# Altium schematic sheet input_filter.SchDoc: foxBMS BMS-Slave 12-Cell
size A3; DocumentNumber: 4; SheetNumber: 4; SheetTotal: 15; AUTHOR: Fraunhofer IISB foxBMS Team; SheetDescription: Primary Voltage Measurement
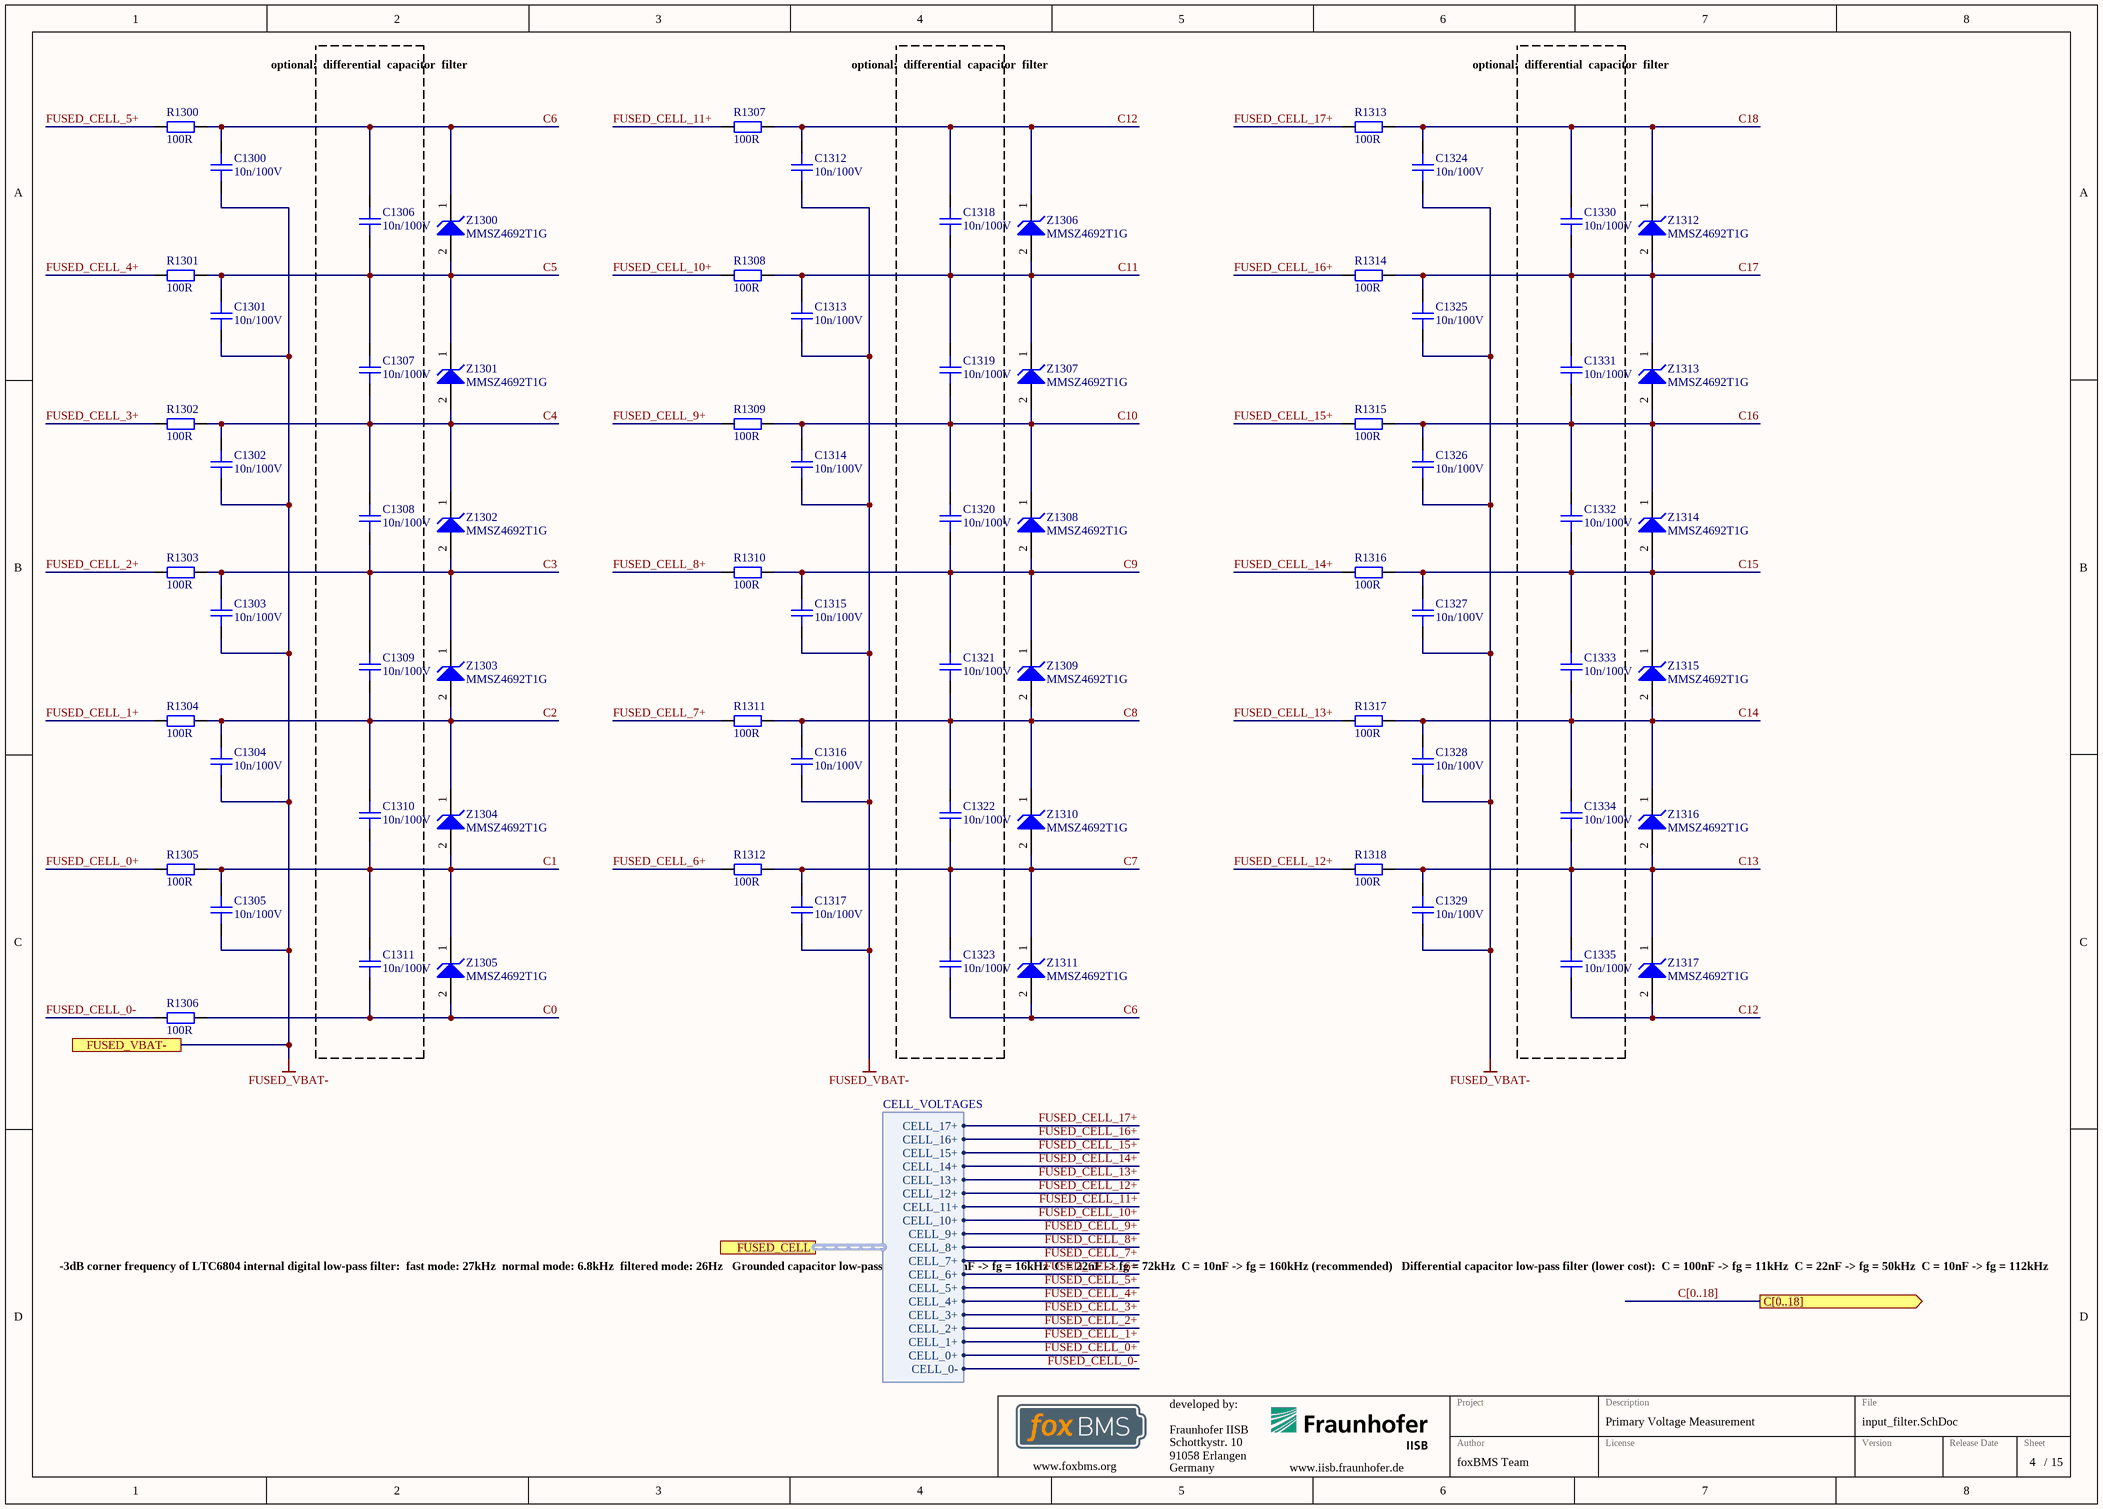
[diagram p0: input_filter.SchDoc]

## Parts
C1300  10n/100V  [CAPC1608X08N]
C1301  10n/100V  [CAPC1608X08N]
C1302  10n/100V  [CAPC1608X08N]
C1303  10n/100V  [CAPC1608X08N]
C1304  10n/100V  [CAPC1608X08N]
C1305  10n/100V  [CAPC1608X08N]
C1306  10n/100V  [CAPC1608X08N]
C1307  10n/100V  [CAPC1608X08N]
C1308  10n/100V  [CAPC1608X08N]
C1309  10n/100V  [CAPC1608X08N]
C1310  10n/100V  [CAPC1608X08N]
C1311  10n/100V  [CAPC1608X08N]
C1312  10n/100V  [CAPC1608X08N]
C1313  10n/100V  [CAPC1608X08N]
C1314  10n/100V  [CAPC1608X08N]
C1315  10n/100V  [CAPC1608X08N]
C1316  10n/100V  [CAPC1608X08N]
C1317  10n/100V  [CAPC1608X08N]
C1318  10n/100V  [CAPC1608X08N]
C1319  10n/100V  [CAPC1608X08N]
C1320  10n/100V  [CAPC1608X08N]
C1321  10n/100V  [CAPC1608X08N]
C1322  10n/100V  [CAPC1608X08N]
C1323  10n/100V  [CAPC1608X08N]
C1324  10n/100V  [CAPC1608X08N]
C1325  10n/100V  [CAPC1608X08N]
C1326  10n/100V  [CAPC1608X08N]
C1327  10n/100V  [CAPC1608X08N]
C1328  10n/100V  [CAPC1608X08N]
C1329  10n/100V  [CAPC1608X08N]
C1330  10n/100V  [CAPC1608X08N]
C1331  10n/100V  [CAPC1608X08N]
C1332  10n/100V  [CAPC1608X08N]
C1333  10n/100V  [CAPC1608X08N]
C1334  10n/100V  [CAPC1608X08N]
C1335  10n/100V  [CAPC1608X08N]
R1300  100R  [RESC1608X05N]
R1301  100R  [RESC1608X05N]
R1302  100R  [RESC1608X05N]
R1303  100R  [RESC1608X05N]
R1304  100R  [RESC1608X05N]
R1305  100R  [RESC1608X05N]
R1306  100R  [RESC1608X05N]
R1307  100R  [RESC1608X05N]
R1308  100R  [RESC1608X05N]
R1309  100R  [RESC1608X05N]
R1310  100R  [RESC1608X05N]
R1311  100R  [RESC1608X05N]
R1312  100R  [RESC1608X05N]
R1313  100R  [RESC1608X05N]
R1314  100R  [RESC1608X05N]
R1315  100R  [RESC1608X05N]
R1316  100R  [RESC1608X05N]
R1317  100R  [RESC1608X05N]
R1318  100R  [RESC1608X05N]
Z1300  MMSZ4692T1G  [ONSC-SOD-123-2-425-04_V]
Z1301  MMSZ4692T1G  [ONSC-SOD-123-2-425-04_V]
Z1302  MMSZ4692T1G  [ONSC-SOD-123-2-425-04_V]
Z1303  MMSZ4692T1G  [ONSC-SOD-123-2-425-04_V]
Z1304  MMSZ4692T1G  [ONSC-SOD-123-2-425-04_V]
Z1305  MMSZ4692T1G  [ONSC-SOD-123-2-425-04_V]
Z1306  MMSZ4692T1G  [ONSC-SOD-123-2-425-04_V]
Z1307  MMSZ4692T1G  [ONSC-SOD-123-2-425-04_V]
Z1308  MMSZ4692T1G  [ONSC-SOD-123-2-425-04_V]
Z1309  MMSZ4692T1G  [ONSC-SOD-123-2-425-04_V]
Z1310  MMSZ4692T1G  [ONSC-SOD-123-2-425-04_V]
Z1311  MMSZ4692T1G  [ONSC-SOD-123-2-425-04_V]
Z1312  MMSZ4692T1G  [ONSC-SOD-123-2-425-04_V]
Z1313  MMSZ4692T1G  [ONSC-SOD-123-2-425-04_V]
Z1314  MMSZ4692T1G  [ONSC-SOD-123-2-425-04_V]
Z1315  MMSZ4692T1G  [ONSC-SOD-123-2-425-04_V]
Z1316  MMSZ4692T1G  [ONSC-SOD-123-2-425-04_V]
Z1317  MMSZ4692T1G  [ONSC-SOD-123-2-425-04_V]

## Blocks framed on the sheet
optional: / differential / capacitor / filter: C1306-C1311
optional: / differential / capacitor / filter: C1318-C1323
optional: / differential / capacitor / filter: C1330-C1335

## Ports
C[0..18] (out), FUSED_CELL (harness CELL_VOLTAGES), FUSED_VBAT-

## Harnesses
CELL_VOLTAGES: CELL_0-, CELL_0+, CELL_1+, CELL_10+, CELL_11+, CELL_12+, CELL_13+, CELL_14+, CELL_15+, CELL_16+, CELL_17+, CELL_2+, CELL_3+, CELL_4+, CELL_5+, CELL_6+, CELL_7+, CELL_8+, CELL_9+

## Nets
FUSED_VBAT-: C1300.2 C1301.2 C1302.2 C1303.2 C1304.2 C1305.2 C1312.2 C1313.2 C1314.2 C1315.2 C1316.2 C1317.2 C1324.2 C1325.2 C1326.2 C1327.2 C1328.2 C1329.2 ; port FUSED_VBAT-
C0: C1311.2 R1306.2 Z1305.2(A)
C1: C1305.1 C1310.2 C1311.1 R1305.2 Z1304.2(A) Z1305.1(K)
C2: C1304.1 C1309.2 C1310.1 R1304.2 Z1303.2(A) Z1304.1(K)
C3: C1303.1 C1308.2 C1309.1 R1303.2 Z1302.2(A) Z1303.1(K)
C4: C1302.1 C1307.2 C1308.1 R1302.2 Z1301.2(A) Z1302.1(K)
C5: C1301.1 C1306.2 C1307.1 R1301.2 Z1300.2(A) Z1301.1(K)
C6: C1300.1 C1306.1 C1323.2 R1300.2 Z1300.1(K) Z1311.2(A)
C7: C1317.1 C1322.2 C1323.1 R1312.2 Z1310.2(A) Z1311.1(K)
C8: C1316.1 C1321.2 C1322.1 R1311.2 Z1309.2(A) Z1310.1(K)
C9: C1315.1 C1320.2 C1321.1 R1310.2 Z1308.2(A) Z1309.1(K)
C10: C1314.1 C1319.2 C1320.1 R1309.2 Z1307.2(A) Z1308.1(K)
C11: C1313.1 C1318.2 C1319.1 R1308.2 Z1306.2(A) Z1307.1(K)
C12: C1312.1 C1318.1 C1335.2 R1307.2 Z1306.1(K) Z1317.2(A)
C13: C1329.1 C1334.2 C1335.1 R1318.2 Z1316.2(A) Z1317.1(K)
C14: C1328.1 C1333.2 C1334.1 R1317.2 Z1315.2(A) Z1316.1(K)
C15: C1327.1 C1332.2 C1333.1 R1316.2 Z1314.2(A) Z1315.1(K)
C16: C1326.1 C1331.2 C1332.1 R1315.2 Z1313.2(A) Z1314.1(K)
C17: C1325.1 C1330.2 C1331.1 R1314.2 Z1312.2(A) Z1313.1(K)
C18: C1324.1 C1330.1 R1313.2 Z1312.1(K)
FUSED_CELL_0+: R1305.1 ; port FUSED_CELL.CELL_0+
FUSED_CELL_0-: R1306.1 ; port FUSED_CELL.CELL_0-
FUSED_CELL_1+: R1304.1 ; port FUSED_CELL.CELL_1+
FUSED_CELL_2+: R1303.1 ; port FUSED_CELL.CELL_2+
FUSED_CELL_3+: R1302.1 ; port FUSED_CELL.CELL_3+
FUSED_CELL_4+: R1301.1 ; port FUSED_CELL.CELL_4+
FUSED_CELL_5+: R1300.1 ; port FUSED_CELL.CELL_5+
FUSED_CELL_6+: R1312.1 ; port FUSED_CELL.CELL_6+
FUSED_CELL_7+: R1311.1 ; port FUSED_CELL.CELL_7+
FUSED_CELL_8+: R1310.1 ; port FUSED_CELL.CELL_8+
FUSED_CELL_9+: R1309.1 ; port FUSED_CELL.CELL_9+
FUSED_CELL_10+: R1308.1 ; port FUSED_CELL.CELL_10+
FUSED_CELL_11+: R1307.1 ; port FUSED_CELL.CELL_11+
FUSED_CELL_12+: R1318.1 ; port FUSED_CELL.CELL_12+
FUSED_CELL_13+: R1317.1 ; port FUSED_CELL.CELL_13+
FUSED_CELL_14+: R1316.1 ; port FUSED_CELL.CELL_14+
FUSED_CELL_15+: R1315.1 ; port FUSED_CELL.CELL_15+
FUSED_CELL_16+: R1314.1 ; port FUSED_CELL.CELL_16+
FUSED_CELL_17+: R1313.1 ; port FUSED_CELL.CELL_17+

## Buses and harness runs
bus C[0..18] = port C[0..18]

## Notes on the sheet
- -3dB corner frequency of LTC6804 internal digital low-pass filter:
  fast mode: 27kHz
  normal mode: 6.8kHz
  filtered mode: 26Hz
  Grounded capacitor low-pass filter:
  C = 100nF -> fg = 16kHz
  C = 22nF -> fg = 72kHz
  C = 10nF -> fg = 160kHz (recommended)
  Differential capacitor low-pass filter (lower cost):
  C = 100nF -> fg = 11kHz
  C = 22nF -> fg = 50kHz
  C = 10nF -> fg = 112kHz

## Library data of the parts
C1300-C1335 = gen_C_ceramic_10n_100V_X7R_0603: MLCC; Capacitance: 10n; Rated Voltage: 100V; Dielectric: X7R; Case EIA: 0603; Case Metric: 1608; Automotive Qualified: True
R1300-R1318 = gen_R_100R_0603: SMD Resistor 100R 0603; Tolerance: 1%; Power: 0.1W; Case EIA: 0603; Case Metric: 1608; Maximum Working Voltage: 75V; PnP Package: R_0603; Automotive Qualified: True
Z1300-Z1317 = CMP-1060-00434-1: Zener Voltage Regulator, 500 mW, 2-Pin SOD-123, Pb-Free, Tape and Reel; Manufacturer: On Semiconductor; VZ Typ (V): 6.8; P Max (W): 0.5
